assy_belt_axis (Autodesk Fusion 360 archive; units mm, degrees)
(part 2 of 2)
joint "Assemble7" alignAngle 0 alignOffsetX 0 alignOffsetY 0 alignOffsetZ 0
joint "Assemble8" alignAngle 0 alignOffsetX 0 alignOffsetY 0 alignOffsetZ 0
fillet "Fillet6" ChordLen 8
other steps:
joint_origin "JointOrigin1"
joint_origin "JointOrigin2"
joint_origin "JointOrigin3"
joint_origin "JointOrigin4"
joint_origin "JointOrigin5"
joint_origin "JointOrigin6"
joint_origin "JointOrigin7"
named bodies: "belt_motor_mount"

design "PP_SWTC_Omron-V154"
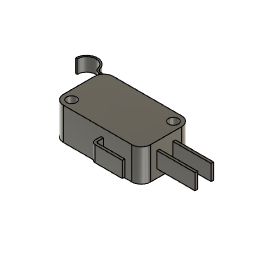
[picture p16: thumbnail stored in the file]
sketch "Sketch1" plane through (0, 0, 0) normal (0, 0, 1) x axis (1, 0, 0)
  line L1 (22.2, 0) -> (0, 0)
  line L2 (22.2, 10.3) -> (22.2, 0)
  line L3 (0, 10.3) -> (22.2, 10.3)
  line L4 (0, 0) -> (0, 10.3)
  line L5 (25, -2.8) -> (-2.8, -2.8)
  line L6 (25, 13.1) -> (25, -2.8)
  line L7 (-2.8, 13.1) -> (25, 13.1)
  line L8 (-2.8, -2.8) -> (-2.8, 13.1)
  line L9 (14.1, 15.2) -> (14.1, 13.1)
  line L10 (-6.9, 15.2) -> (14.1, 15.2)
  line L11 (13.6, 14.7) -> (-7.442, 14.7)
  line L12 (13.6, 13.1) -> (13.6, 14.7)
  line L13 (-13.9, 15.2) -> (-13.4, 15.2)
  line L14 (-10.4, 18.7) -> (-10.4, 15.2)
  line L15 (37.2, 8.1) -> (25, 8.1)
  line L16 (37.2, 7.3) -> (37.2, 8.1)
  line L17 (25, 7.3) -> (37.2, 7.3)
  line L18 (25, 8.1) -> (25, 7.3)
  line L19 (37.2, 3) -> (25, 3)
  line L20 (37.2, 2.2) -> (37.2, 3)
  line L21 (25, 2.2) -> (37.2, 2.2)
  line L22 (25, 3) -> (25, 2.2)
  line L23 (13, -5.2) -> (13, -2.8)
  line L24 (22.2, -5.2) -> (13, -5.2)
  line L25 (22.2, -6) -> (22.2, -5.2)
  line L26 (12.2, -6) -> (22.2, -6)
  line L27 (12.2, -2.8) -> (12.2, -6)
  circle C1 centre (0, 0) radius 2.8
  circle C2 centre (22.2, 10.3) radius 2.8
  circle C3 centre (22.2, 10.3) radius 1.55
  circle C4 centre (0, 0) radius 1.55
  arc A1 centre (-10.4, 15.2) radius 3.5 clockwise from (-13.9, 15.2) to (-6.9, 15.2)
  arc A2 centre (-10.4, 15.2) radius 3 clockwise from (-13.4, 15.2) to (-7.442, 14.7)
  point P1 (0, 0)
  point P2 (0, 0)
  point P10 (0, 0)
  point P4 (22.2, 10.3)
  point P11 (22.2, 10.3)
  point P13 (0, 0)
  point P14 (14.1, 13.1)
  point P18 (-13.9, 15.2)
  point P17 (-10.4, 15.2)
  point P19 (-10.4, 15.2)
  point P23 (13.6, 13.1)
  point P24 (-10.4, 15.2)
  point P25 (-10.4, 18.7)
  point P26 (25, 8.1)
  point P30 (25, 3)
  point P34 (13, -2.8)
  point P39 (12.2, -2.8)
  point P31 (37.2, 3)
  point P3 (22.2, 0)
  point P6 (-2.8, -2.8)
  point P7 (25, -2.8)
  point P9 (-2.8, 13.1)
  point P8 (25, 13.1)
  point P12 (22.2, 10.3)
  point P22 (13.6, 14.7)
  point P15 (14.1, 15.2)
  point P35 (13, -5.2)
  point P32 (37.2, 2.2)
  point P27 (37.2, 8.1)
  point P28 (37.2, 7.3)
  point P37 (22.2, -6)
  horizontal L1
  vertical L2
  horizontal L3
  vertical L4
  coincident P1 P2
  horizontal L5
  vertical L6
  horizontal L7
  vertical L8
  coincident P1 P10
  coincident P4 P11
  concentric C2 C3
  coincident P1 P13
  equal C3 C4
  tangent L7 C2
  tangent L6 C2
  tangent L5 C1
  coincident L7 P14
  perpendicular L7 L9
  perpendicular L9 L10
  coincident L10 P18
  coincident P17 P19
  horizontal L11
  coincident L7 P23
  perpendicular L7 L12
  coincident P19 L13
  horizontal L13
  coincident P19 P24
  midpoint A1 P25
  horizontal L15
  vertical L16
  horizontal L17
  vertical L18
  coincident L6 P26
  horizontal L19
  vertical L20
  horizontal L21
  vertical L22
  coincident L6 P30
  coincident L5 P34
  perpendicular L5 L23
  perpendicular L6 L24
  perpendicular L24 L25
  perpendicular L25 L26
  coincident L5 P39
  perpendicular L5 L27
  coincident L16 P31
  dimension "d2" distance P2 P3 = 22.2
  dimension "d3" distance P3 P4 = 10.3
  dimension "d4" distance P6 P7 = 27.8
  dimension "d5" distance P6 P9 = 15.9
  dimension "d6" diameter C3 = 3.1
  dimension "d7" distance P8 P12 = 2.8
  dimension "d8" distance L9 L12 = 0.5
  dimension "d9" distance L10 P22 = 0.5 (= "d8")
  dimension "d10" distance A1 A2 = 0.5 (= "d8")
  dimension "d11" radius A1 = 3.5
  dimension "d12" distance P10 P25 = 18.7
  dimension "d13" distance P12 P25 = 32.6
  dimension "d14" distance P12 P15 = 8.1
  dimension "d25" distance P35 L27 = 0.8
  dimension "d26" distance P35 L26 = 0.8 (= "d25")
  dimension "d27" distance P31 P32 = 0.8 (= "d25")
  dimension "d28" distance P27 P28 = 0.8 (= "d25")
  dimension "d29" distance P8 P37 = 19.1
  dimension "d30" distance P7 P37 = 2.8
  dimension "d31" distance P7 L23 = 12
  dimension "d33" distance P8 P27 = 5
  dimension "d34" distance P6 P28 = 40
  dimension "d35" distance P7 P32 = 5 (= "d33")
extrude "Extrude1" new body sketch "Sketch1" profile of L5 L6 L7 L8 C3 C4 distance 10.3
extrude "Extrude2" add sketch "Sketch1" profile of L7 L9 L10 A1 A2 L11 L12 L13 distance 4.3
fillet "Fillet1" radius 3
fillet "Fillet2" radius 1
fillet "Fillet3" radius 1.5
extrude "Extrude3" add sketch "Sketch1" profile of L5 L6 L15 L16 L17 L18 L19 L20 L21 L22 L23 L24 L25 L26 L27 distance 5
fillet "Fillet4" radius 0.5
fillet "Fillet5" radius 1.3 (= "0.5 mm + 0.8 mm")

design "carriage_front_generic" references "PP_TRNS_V-Wheel", "HW_M5x20-SHCS"
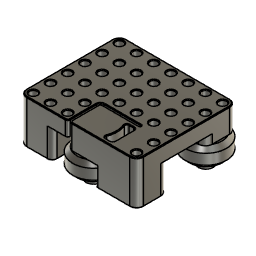
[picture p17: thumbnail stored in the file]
parameter "d19" = 10.75
sketch "Sketch1" plane through (0, 0, 0) normal (0, 0, 1) x axis (1, 0, 0)
  line L1 (0, -29) -> (0, 29)
  line L2 (-34, 29) -> (0, 29)
  line L3 (-34, -29) -> (-34, 29)
  line L4 (0, 10) -> (-34, 10)
  line L5 (0, -10) -> (-34, -10)
  line L6 (-16.2, 11) -> (-34, 11)
  line L7 (-16.2, 29) -> (-16.2, 11)
  line L8 (-34, -29) -> (0, -29)
  line L9 (34, -29) -> (0, -29)
  line L10 (34, -29) -> (34, 29)
  line L11 (16.2, 11) -> (34, 11)
  line L12 (16.2, 29) -> (16.2, 11)
  line L13 (34, 29) -> (0, 29)
  line L14 (17.9222, -13.2) -> (11.9222, -13.2)
  line L15 (17.9222, -26.8) -> (17.9222, -13.2)
  line L16 (11.9791, -26.8) -> (17.9222, -26.8)
  line L17 (-5, -11) -> (17.9222, -11)
  line L18 (17.9222, -10) -> (17.9222, -11)
  line L19 (-6, -10) -> (17.9222, -10)
  line L20 (-6, -29) -> (-6, -10)
  line L21 (34, -11) -> (17.9222, -11)
  line L22 (-5, -29) -> (-5, -11)
  line L23 (12.75, -20.05) -> (0, -20.05)
  line L24 (13.75, -20.05) -> (12.75, -20.05)
  line L25 (30, -25) -> (30, -15)
  line L26 (-30, -25) -> (30, -25)
  line L27 (-15, -11) -> (-34, -11)
  line L28 (-15, -29) -> (-15, -11)
  circle C1 centre (-25.1, 20.1) radius 2.2
  circle C2 centre (0, -20.05) radius 2.2
  circle C3 centre (0, -20.05) radius 12
  circle C4 centre (-25.1, 20.1) radius 12
  circle C5 centre (-25.1, 20.1) radius 4.2
  circle C6 centre (0, -20.05) radius 4.2
  circle C7 centre (0, 25) radius 2.2
  circle C8 centre (25.1, 20.1) radius 4.2
  circle C9 centre (25.1, 20.1) radius 2.2
  arc A1 centre (0, -20.05) radius 12.75 clockwise from (8.9811, -11) to (9.0807, -29)
  arc A2 centre (0, -20.05) radius 13.75 clockwise from (11.9222, -13.2) to (11.9791, -26.8)
  circle C10 centre (-30, -25) radius 2.2
  circle C11 centre (30, -25) radius 2.2
  circle C12 centre (30, -15) radius 2.2
  point P1 (0, 0)
  point P10 (-34, 10)
  point P11 (0, 10)
  point P13 (0, -10)
  point P14 (-34, 11)
  point P16 (-16.2, 29)
  point P19 (0, 25)
  point P9 (-34, -29)
  point P20 (-34, -29)
  point P12 (-34, -10)
  point P18 (0, -20.05)
  point P2 (0, 29)
  point P30 (0, 29)
  point P3 (0, -29)
  point P21 (0, -29)
  point P8 (-34, 29)
  point P23 (34, 29)
  point P24 (34, -29)
  point P27 (34, 11)
  point P15 (-16.2, 11)
  point P28 (16.2, 11)
  point P29 (16.2, 29)
  point P22 (34, -29)
  point P39 (-6, -29)
  point P32 (17.9222, -13.2)
  point P40 (34, -11)
  point P41 (-5, -29)
  point P43 (9.0807, -29)
  point P44 (8.9811, -11)
  point P42 (0, -20.05)
  point P5 (0, -20.05)
  point P45 (0, -20.05)
  point P46 (12.75, -20.05)
  point P47 (0, -20.05)
  point P31 (11.9222, -13.2)
  point P48 (11.9222, -13.2)
  point P49 (13.75, -20.05)
  point P52 (30, -15)
  point P53 (30, -15)
  point P51 (30, -25)
  point P54 (30, -25)
  point P55 (30, -25)
  point P50 (-30, -25)
  point P56 (-30, -25)
  point P57 (-34, -11)
  point P36 (-5, -11)
  point P59 (-15, -29)
  point P4 (-25.1, 20.1)
  point P17 (-25.1, 20.1)
  point P35 (17.9222, -11)
  point P37 (17.9222, -10)
  point P6 (0, -20.05)
  vertical L1
  coincident P1 L1
  equal C1 C2
  concentric C2 C3
  concentric C1 C4
  equal C3 C4
  perpendicular L1 L2
  perpendicular L2 L3
  midpoint P1 L1
  coincident L3 P10
  coincident L1 P11
  perpendicular L1 L4
  coincident L1 P13
  perpendicular L1 L5
  coincident L3 P14
  coincident L2 P16
  perpendicular L2 L7
  concentric C1 C5
  concentric C3 C6
  equal C5 C6
  coincident L1 P19
  perpendicular L1 L8
  coincident P9 P20
  coincident L3 P12
  horizontal L6
  coincident L1 P18
  symmetric P2 L1 P30
  symmetric P3 L1 P21
  symmetric L1 C1 C9
  symmetric L1 P8 P23
  symmetric L1 P9 P24
  symmetric L1 P14 P27
  symmetric L1 P15 P28
  symmetric L1 P16 P29
  symmetric L1 C5 C8
  symmetric L1 P20 P22
  horizontal L14
  vertical L15
  horizontal L16
  horizontal L17
  perpendicular L17 L18
  perpendicular L18 L19
  coincident L8 P39
  perpendicular L8 L20
  coincident P32 L18
  coincident L10 P40
  perpendicular L10 L21
  coincident L8 P41
  perpendicular L8 L22
  coincident L9 P43
  coincident L17 P44
  coincident P18 P42
  coincident P5 P45
  coincident A1 P46
  coincident P42 P47
  coincident P31 P48
  coincident A2 P49
  parallel L23 L24
  horizontal L23
  equal C10 C11
  coincident P52 P53
  coincident P51 P54
  vertical L25
  coincident P51 P55
  coincident P50 P56
  horizontal L26
  equal C11 C12
  coincident L3 P57
  perpendicular L3 L27
  coincident P36 L27
  coincident L8 P59
  perpendicular L8 L28
  dimension "d1" distance P1 P4 = 20.1
  dimension "d2" distance P1 P5 = 20.05 (= "d1 - 0.05 mm")
  dimension "d3" diameter C1 = 4.4
  dimension "d4" diameter C4 = 24
  dimension "d11" distance P2 P8 = 34
  dimension "d17" distance P1 L4 = 10
  dimension "d18" distance P1 P13 = 10
  dimension "d28" distance C1 C5 = 2
  dimension "d73" diameter C7 = 4.4
  dimension "d76" distance P1 P19 = 25
  dimension "d133" distance P2 P19 = 4
  dimension "d134" distance P2 P4 = 25.1
  dimension "d135" distance P1 P2 = 29
  dimension "d136" distance P4 L2 = 8.9
  dimension "d137" distance P8 P17 = 8.9 (= "d136")
  dimension "d138" distance L7 P17 = 8.9 (= "d137")
  dimension "d139" distance P10 L6 = 1
  dimension "d140" distance L9 L16 = 2.2
  dimension "d141" distance L14 L17 = 2.2 (= "d140")
  dimension "d142" distance P31 P32 = 6
  dimension "d143" distance L5 L17 = 1
  dimension "d146" distance C3 A1 = 0.75
  dimension "d147" distance P46 P49 = 1
  dimension "d148" distance P35 P37 = 1
  dimension "d154" distance P6 L8 = 8.95
  dimension "d155" distance P6 L22 = 5
  dimension "d156" distance L20 P41 = 1 (= "d148")
  dimension "d167" distance P1 P50 = 25
  dimension "d168" distance L1 P50 = 30
  dimension "d169" diameter C10 = 4.4
  dimension "d192" distance P21 P51 = 30
  dimension "d193" distance P53 P54 = 10
  dimension "d202" distance P50 L28 = 15
extrude "Extrude1" new body sketch "Sketch1" profile of C1 C2 L2 L3 L6 L7 C5 C6 C7 L8 L9 L10 C8 C9 L11 L12 L13 L14 L15 L16 L17 L18 L19 L20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 blind 9 from offset 11
extrude "Extrude2" add sketch "Sketch1" profile of C1 C2 L2 L3 L6 L7 C5 C6 L8 L9 L10 C8 C9 L11 L12 L13 L14 L15 L16 L17 L21 L22 to an object from offset 5.5 (= "( 11 / 2 ) * 1 mm")
extrude "Extrude3" sketch "Sketch1" profile of L2 L3 L6 L7 C5 C6 L8 L9 L10 C8 L11 L12 L13 L14 L15 L16 L17 L21 L22 blind 0.6
extrude "Extrude5" sketch "Sketch1" profile of L9 L10 L14 L15 L16 L17 L21 A1 A2 to an object offset 11
fillet "Fillet4" ChordLen 2
fillet "Fillet2" radius 4
fillet "Fillet3" radius 4
chamfer "Chamfer3" distance 0.5
fillet "Fillet5" ChordLen 2
fillet "Fillet6" ChordLen 3
fillet "Fillet7" ChordLen 0.5
extrude "Extrude6" sketch "Sketch1" profile of C10 to an object
rectangular_pattern "R-Pattern3" uSpaceDistance 10 vSpaceDistance 10
extrude "Extrude7" sketch "Sketch1" profile of C1 C2 C9 blind -1
extrude "Extrude8" sketch "Sketch1" profile of L3 L8 C10 L27 to an object
fillet "Fillet8" ChordLen 6
extrude "Extrude9" cut of existing geometry to an object
extrude "Extrude10" cut of existing geometry to an object
chamfer "Chamfer4" distance 2.2
fillet "Fillet9" ChordLen 4
chamfer "Chamfer5" distance 0.4
chamfer "Chamfer6" distance 0.4
chamfer "Chamfer7" distance 0.5
component_insert "Component Insert3"
component_insert "Component Insert4"
component_insert "Component Insert5"
component_insert "Component Insert11"
component_insert "Component Insert12"
component_insert "Component Insert14"
joint "Assemble14" alignAngle 0 alignOffsetX 0 alignOffsetY 0 alignOffsetZ 0
joint "Assemble17" alignAngle 180 alignOffsetX 0 alignOffsetY 0 alignOffsetZ 0
joint "Assemble18" alignAngle 0 alignOffsetX 0 alignOffsetY 0 alignOffsetZ 0
joint "Assemble19" alignAngle 0 alignOffsetX 0 alignOffsetY 0 alignOffsetZ 0
joint "Assemble21" alignAngle 0 alignOffsetX 0 alignOffsetY 0 alignOffsetZ 0
joint "Assemble22" alignAngle 0 alignOffsetX 0 alignOffsetY 0 alignOffsetZ 0
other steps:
joint_origin "JointOrigin12"
joint_origin "JointOrigin15"
joint_origin "JointOrigin16"
named bodies: "carriage_front_generic"

design "HW_M5-Washer"
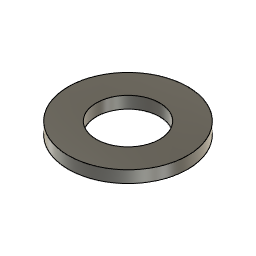
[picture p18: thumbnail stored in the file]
sketch "Sketch1" plane through (0, 0, 0) normal (0, 1, 0) x axis (1, 0, 0)
  line L1 (5, 0) -> (2.65, 0)
  line L2 (5, -1) -> (5, 0)
  line L3 (2.65, -1) -> (5, -1)
  line L4 (2.65, 0) -> (2.65, -1)
  point P1 (0, 0)
  point P2 (2.65, 0)
  point P5 (2.65, -1)
  horizontal L1
  vertical L2
  horizontal L3
  vertical L4
  coincident P1 L1
  dimension "d1" distance P2 P5 = 1
  dimension "d2" distance P1 L4 = 2.65 (= "( 5.3 / 2 ) * 1 mm")
  dimension "d3" distance P1 L2 = 5 (= "( 10 / 2 ) * 1 mm")
revolve "Revolve1" sketch "Sketch1" AlongAngle 360

design "PP_TRNS_GT2-Pulley-20T-6mm"
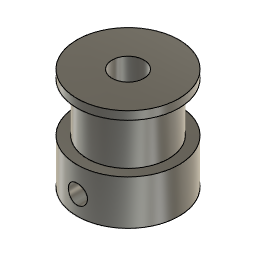
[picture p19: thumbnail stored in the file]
sketch "Sketch1" plane through (0, 0, 0) normal (0, 1, 0) x axis (1, 0, 0)
  line L1 (8, 0) -> (0, 0)
  line L2 (8, -7) -> (8, 0)
  line L3 (6.3662, -7) -> (8, -7)
  line L4 (6.3662, -14.7) -> (6.3662, -7)
  line L5 (8, -14.7) -> (6.3662, -14.7)
  line L6 (8, -16) -> (8, -14.7)
  line L7 (2.5, -16) -> (8, -16)
  line L8 (2.5, 0) -> (2.5, -16)
  line L9 (0, -3) -> (0, 0)
  circle C1 centre (0, -3) radius 1.5
  point P1 (0, 0)
  point P2 (0, 0)
  point P10 (2.5, 0)
  point P4 (8, -7)
  point P12 (0, 0)
  point P11 (0, -3)
  point P13 (0, -3)
  point P3 (8, 0)
  point P7 (8, -14.7)
  point P8 (8, -16)
  coincident P1 P2
  horizontal L1
  perpendicular L1 L2
  perpendicular L2 L3
  perpendicular L3 L4
  perpendicular L4 L5
  perpendicular L5 L6
  perpendicular L4 L7
  coincident L1 P10
  perpendicular L1 L8
  coincident P4 L6
  coincident P1 P12
  coincident P11 P13
  vertical L9
  dimension "d1" distance P1 L8 = 2.5 (= "( 5 / 2 ) * 1 mm")
  dimension "d2" distance P1 L2 = 8 (= "( 16 / 2 ) * 1 mm")
  dimension "d3" distance P3 P4 = 7
  dimension "d4" distance P1 L4 = 6.3662 (= "( 20 * 2 / PI ) * 1 mm / 2")
  dimension "d5" distance P7 P8 = 1.3
  dimension "d6" distance P3 L7 = 16
  dimension "d8" diameter C1 = 3
  dimension "d9" distance P12 P13 = 3
revolve "Revolve1" sketch "Sketch1" AlongAngle 360
extrude "Extrude1" cut sketch "Sketch1" profile of C1 against normal blind 17

design "belt_idler" references "HW_M5-Washer", "PP_BRNG_625F-5x16x5", "HW_M5x10-SHCS", "HW_M5x20-SHCS"
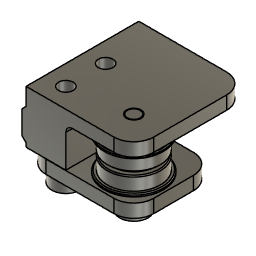
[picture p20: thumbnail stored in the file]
sketch "Sketch1" plane through (0, 0, 0) normal (0, 0, 1) x axis (1, 0, 0)
  line L1 (0, 0) -> (23.5, 0)
  line L2 (0, 25) -> (0, -9)
  line L3 (32.5, 25) -> (0, 25)
  line L4 (32.5, -9) -> (32.5, 25)
  line L5 (0, -9) -> (32.5, -9)
  line L6 (5, 25) -> (5, -9)
  line L7 (12, 25) -> (12, -9)
  line L8 (6, 9) -> (6, -3)
  line L9 (0, 15) -> (12, 15)
  line L10 (32.5, 15) -> (12, 15)
  circle C1 centre (23.5, 0) radius 8.5
  circle C2 centre (23.5, 0) radius 7.5
  circle C3 centre (23.5, 0) radius 2.55
  circle C4 centre (23.5, 0) radius 3.55
  circle C5 centre (23.5, 0) radius 2.2
  circle C6 centre (6, -3) radius 2.2
  circle C7 centre (6, -3) radius 5
  circle C8 centre (6, -3) radius 2.75
  circle C9 centre (6, 9) radius 2.75
  circle C10 centre (6, 9) radius 2.2
  circle C11 centre (6, 9) radius 5
  point P2 (23.5, 0)
  point P3 (23.5, 0)
  point P4 (23.5, 0)
  point P1 (0, 0)
  point P5 (0, 0)
  point P6 (15, 0)
  point P7 (0, -9)
  point P11 (0, -9)
  point P12 (23.5, 0)
  point P15 (5, -9)
  point P16 (5, 25)
  point P18 (12, -9)
  point P19 (12, 25)
  point P22 (6, -3)
  point P26 (6, -3)
  point P24 (6, 9)
  point P27 (6, 9)
  point P28 (12, 15)
  point P29 (0, 15)
  point P30 (6, 3)
  point P31 (32.5, 15)
  point P13 (23.5, 0)
  point P9 (32.5, 25)
  point P10 (32.5, -9)
  point P21 (6, -3)
  point P23 (6, 9)
  coincident P2 P3
  coincident P2 P4
  coincident P1 P5
  horizontal L1
  coincident C1 P6
  coincident L1 P6
  perpendicular L2 L3
  perpendicular L3 L4
  perpendicular L4 L5
  coincident P7 P11
  coincident P2 P12
  concentric C2 C3
  coincident P1 L2
  vertical L2
  concentric C1 C4
  coincident L5 P15
  coincident L3 P16
  perpendicular L3 L6
  concentric C1 C5
  coincident L5 P18
  coincident L3 P19
  perpendicular L3 L7
  concentric C6 C7
  concentric C6 C8
  concentric C9 C10
  concentric C9 C11
  equal C7 C11
  coincident P22 P26
  coincident P24 P27
  vertical L8
  equal C6 C10
  equal C8 C9
  coincident L7 P28
  coincident L2 P29
  perpendicular L2 L9
  midpoint L8 P30
  coincident L4 P31
  perpendicular L4 L10
  dimension "d2" distance P1 P6 = 15
  dimension "d38" distance C1 C2 = 1
  dimension "d39" diameter C2 = 15
  dimension "d40" diameter C3 = 5.1
  dimension "d41" distance L4 P13 = 9
  dimension "d42" distance L5 P13 = 9
  dimension "d43" distance C3 C4 = 1
  dimension "d44" distance P7 P15 = 5
  dimension "d46" distance P9 P10 = 34
  dimension "d48" diameter C5 = 4.4
  dimension "d63" distance P6 L7 = 3
  dimension "d64" diameter C7 = 10
  dimension "d65" diameter C6 = 4.4
  dimension "d66" diameter C8 = 5.5
  dimension "d67" distance P7 P22 = 6
  dimension "d68" distance P7 P21 = 6
  dimension "d69" distance P26 P27 = 12
  dimension "d78" distance P23 L9 = 6
extrude "Extrude1" new body sketch "Sketch1" profile of L2 L3 L4 L5 C3 C4 L6 C5 L7 C6 C8 C9 C10 L9 L10 along normal blind 4 bodies "belt_idler_body"
extrude "Extrude2" sketch "Sketch1" profile of L2 L3 L5 L6 blind -20
extrude "Extrude4" add sketch "Sketch1" profile of C3 C4 C5 against normal blind 0.5
chamfer "Chamfer5" distance 0.4 distance 1
component_insert "Component Insert3"
joint "Assemble3" alignAngle 0 alignOffsetX 0 alignOffsetY 0 alignOffsetZ 0
component_insert "Component Insert4"
joint "Assemble4" alignAngle 0 alignOffsetX 0 alignOffsetY 0 alignOffsetZ 0
component_insert "Component Insert5"
joint "Assemble5" alignAngle 0 alignOffsetX 0 alignOffsetY 0 alignOffsetZ 0
extrude "Extrude5" add sketch "Sketch1" profile of L3 L5 L6 L7 C6 C8 C9 C10 to an object
sketch "Sketch2" plane through (0, 0, 0) normal (-1, 0, 0) x axis (0, -1, 0)
  line L1 (9, 4) -> (9, -16)
  line L2 (-25, 4) -> (9, 4)
  line L3 (-25, -16) -> (-25, 4)
  line L4 (9, -16) -> (-25, -16)
  line L5 (-25, -6) -> (9, -6)
  line L6 (-3, -6) -> (-3, 0)
  line L7 (-19, -12.7175) -> (-22.3588, -9.3588)
  line L8 (-15.6412, -9.3588) -> (-19, -12.7175)
  line L9 (-19, -6) -> (-19, -12.7175)
  line L10 (-19, -9.8891) -> (-20.9445, -7.9445)
  line L11 (-19, -9.8891) -> (-17.0555, -7.9445)
  circle C1 centre (-19, -6) radius 2.75
  circle C2 centre (-19, -6) radius 4.75
  circle C3 centre (-3, -6) radius 2.75
  circle C4 centre (-3, -6) radius 4.75
  point P6 (9, -6)
  point P7 (-25, -6)
  point P8 (-19, -6)
  point P10 (-3, -6)
  point P12 (-3, 0)
  point P13 (-3, 0)
  point P11 (-3, -6)
  point P14 (-3, -6)
  point P15 (-22.3588, -9.3588)
  point P17 (-15.6412, -9.3588)
  point P18 (-19, -6)
  point P19 (-20.9445, -7.9445)
  point P20 (-19, -9.8891)
  point P21 (-17.0555, -7.9445)
  point P4 (-25, 4)
  point P9 (-19, -6)
  midpoint L1 P6
  midpoint L3 P7
  coincident L5 P8
  concentric C1 C2
  coincident L5 P10
  concentric C3 C4
  equal C2 C4
  equal C1 C3
  coincident P12 P13
  coincident P11 P14
  vertical L6
  coincident C2 P15
  tangent C2 L7
  coincident C2 P17
  tangent C2 L8
  perpendicular L7 L8
  coincident P8 P18
  vertical L9
  coincident C1 P19
  coincident L9 P20
  tangent C1 L10
  coincident C1 P21
  perpendicular L10 L11
  tangent C1 L11
  dimension "d17" distance P4 P9 = 6
  dimension "d19" diameter C1 = 5.5
  dimension "d20" diameter C2 = 9.5
extrude "Extrude3" cut sketch "Sketch2" profile of C1 L10 L11 no distance stored
extrude "Extrude6" cut sketch "Sketch2" profile of C1 C2 L7 L8 L10 L11 no distance stored from offset -5
extrude "Extrude7" sketch "Sketch1" profile of L6 C6 C10 to an object
extrude "Extrude8" sketch "Sketch1" profile of L2 L5 L6 L7 C6 C8 C9 C10 L9 blind 4.1
offset_faces "OffsetFaces1" distance -0.1
extrude "Extrude9" sketch "Sketch1" profile of L2 L4 L5 C3 C4 L6 L7 C8 C9 L9 L10 blind 4 bodies "belt_idler_cap"
extrude "Extrude10" sketch "Sketch1" profile of C3 C4 blind 0.5
fillet "Fillet4" radius 1
fillet "Fillet5" radius 6
fillet "Fillet6" radius 6
fillet "Fillet7" radius 2
sketch "Sketch4" plane through (0, 25, 0) normal (0, 1, 0) x axis (-1, 0, 0)
  line L1 (-26.5, 0) -> (-26.5, 4)
  line L2 (-14, 0) -> (-26.5, 0)
  line L3 (-12, -16) -> (-12, -2)
  line L4 (0, -16) -> (-12, -16)
  line L5 (0, 4) -> (0, -16)
  line L6 (-26.5, 4) -> (0, 4)
  line L7 (2, -6) -> (0, -6)
  line L8 (2, -8.75) -> (0, -10.75)
  line L9 (2, -3.25) -> (2, -8.75)
  line L10 (0, -1.25) -> (2, -3.25)
  line L11 (1.25, -2.5) -> (1.25, -9.5)
  arc A1 centre (-14, -2) radius 2 clockwise from (-14, 0) to (-12, -2)
  point P10 (0, -6)
  point P12 (0, -10.75)
  point P15 (0, -1.25)
  point P11 (2, -6)
  point P16 (1.25, -9.5)
  point P17 (1.25, -2.5)
  point P13 (2, -8.75)
  point P14 (2, -3.25)
  midpoint L5 P10
  perpendicular L5 L7
  coincident L5 P12
  parallel L5 L9
  coincident L5 P15
  perpendicular L8 L10
  midpoint P11 L9
  coincident L8 P16
  vertical L11
  coincident L10 P17
  dimension "d112" distance P10 P11 = 2
  dimension "d113" angle L8 L9 = 45
  dimension "d114" distance P10 L11 = 1.25
  dimension "d115" distance P13 P14 = 5.5
extrude "Extrude11" add sketch "Sketch4" profile of L5 L8 L10 L11 to an object
extrude "Extrude12" cut of existing geometry blind -10
fillet "Fillet8" ChordLen 0.5
component_insert "Component Insert9"
joint "Assemble9" alignAngle 0 alignOffsetX 0 alignOffsetY 0 alignOffsetZ 0
component_insert "Component Insert10"
component_insert "Component Insert11"
joint "Assemble10" alignAngle 0 alignOffsetX 0 alignOffsetY 0 alignOffsetZ 0
joint "Assemble11" alignAngle 0 alignOffsetX 0 alignOffsetY 0 alignOffsetZ 0
component_insert "Component Insert12"
joint "Assemble12" alignAngle 0 alignOffsetX 0 alignOffsetY 0 alignOffsetZ 0
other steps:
joint_origin "JointOrigin2"
joint_origin "JointOrigin6"
joint_origin "JointOrigin7"
joint_origin "JointOrigin8"
joint_origin "JointOrigin9"
named bodies: "belt_idler_body", "belt_idler_cap"

design "HW_M3x16-SHCS"
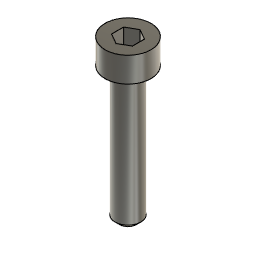
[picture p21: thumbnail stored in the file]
sketch "Sketch1" plane through (0, 0, 0) normal (0, 1, 0) x axis (1, 0, 0)
  line L1 (0, 16) -> (0, -3)
  line L2 (1.05, 16) -> (0, 16)
  line L3 (1.55, 15.5) -> (1.05, 16)
  line L4 (1.55, 0) -> (1.55, 15.5)
  line L5 (2.75, 0) -> (1.55, 0)
  line L6 (2.75, -3) -> (2.75, 0)
  line L7 (0, -3) -> (2.75, -3)
  point P1 (0, 0)
  point P4 (1.05, 16)
  point P5 (1.55, 15.5)
  point P3 (0, 16)
  point P7 (2.75, 0)
  point P8 (2.75, -3)
  point P2 (0, -3)
  vertical L1
  perpendicular L1 L2
  perpendicular L2 L4
  perpendicular L4 L5
  perpendicular L5 L6
  horizontal L7
  coincident P1 L1
  coincident P1 L5
  dimension "d1" distance P1 L2 = 16
  dimension "d2" angle L2 L3 = 45
  dimension "d3" distance P4 P5 = 0.5
  dimension "d4" distance P3 L4 = 1.55 (= "( 3.1 / 2 ) * 1 mm")
  dimension "d5" distance P7 P8 = 3
  dimension "d6" distance P2 P8 = 2.75 (= "( 5.5 / 2 ) * 1 mm")
revolve "Revolve1" sketch "Sketch1" AlongAngle 360
sketch "Sketch2" plane through (0, 0, 3) normal (0, 0, 1) x axis (-1, 0, 0)
  line L1 (0, -1.4434) -> (-1.25, -0.7217)
  line L2 (1.25, -0.7217) -> (0, -1.4434)
  line L3 (1.25, 0.7217) -> (1.25, -0.7217)
  line L4 (0, 1.4434) -> (1.25, 0.7217)
  line L5 (-1.25, 0.7217) -> (0, 1.4434)
  line L6 (-1.25, -0.7217) -> (-1.25, 0.7217)
  circle C1 centre (0, 0) radius 2.75
  point P1 (0, 0)
  point P9 (0, 0)
  point P5 (1.25, -0.7217)
  coincident P1 P9
  vertical L6
  dimension "d8" distance P5 L6 = 2.5
extrude "Extrude1" cut sketch "Sketch2" profile of L1 L2 L3 L4 L5 L6 against normal blind 2

design "belt_clip_update" references "HW_M5x25-SHCS", "HW_M5x10-SHCS"
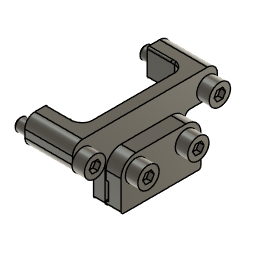
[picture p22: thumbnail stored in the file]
sketch "Sketch1" plane through (0, 0, 0) normal (0, 0, 1) x axis (1, 0, 0)
  line L1 (0, 29) -> (0, 0)
  line L2 (25.5, 29) -> (0, 29)
  line L3 (25.5, 0) -> (25.5, 29)
  line L4 (0, 0) -> (25.5, 0)
  line L5 (20.5, 29) -> (20.5, 0)
  line L6 (19.1, 0) -> (19.1, 29)
  line L7 (19.5, 29) -> (19.5, 0)
  line L8 (1, 29) -> (1, 0)
  line L9 (4.5, 29) -> (4.5, 0)
  line L10 (20.5, 1) -> (19.1, 1)
  line L11 (19.75, 0.7402) -> (19.75, 1)
  line L12 (21.5, 1) -> (20.5, 1)
  line L13 (21.5, 0) -> (21.5, 1)
  line L14 (21.5, 29) -> (21.5, 1)
  line L15 (9.5, 0) -> (9.5, 29)
  line L16 (25.5, 25) -> (0, 25)
  arc A1 centre (19.945, 0) radius 0.555 clockwise from (20.1882, 0.4989) to (20.5, 0)
  arc A2 centre (19.75, -0.4) radius 1 clockwise from (19.8804, 0.5915) to (20.1882, 0.4989)
  arc A3 centre (19.9, 0.7402) radius 0.15 clockwise from (19.8804, 0.5915) to (19.75, 0.7402)
  point P1 (0, 0)
  point P2 (0, 0)
  point P6 (0, 0)
  point P7 (20.5, 0)
  point P8 (20.5, 29)
  point P9 (19.1, 29)
  point P10 (19.1, 0)
  point P11 (19.5, 0)
  point P12 (19.5, 29)
  point P13 (1, 0)
  point P14 (1, 29)
  point P15 (4.5, 0)
  point P16 (4.5, 29)
  point P17 (19.1, 1)
  point P18 (20.5, 1)
  point P19 (19.75, 1)
  point P27 (21.5, 0)
  point P28 (21.5, 29)
  point P29 (9.5, 29)
  point P30 (9.5, 0)
  point P31 (0, 25)
  point P32 (25.5, 25)
  point P4 (25.5, 29)
  point P24 (19.75, -0.4)
  point P26 (21.5, 1)
  coincident P1 P2
  vertical L1
  perpendicular L1 L2
  perpendicular L2 L3
  perpendicular L3 L4
  coincident P1 P6
  coincident L4 P7
  coincident L2 P8
  perpendicular L2 L5
  coincident L2 P9
  coincident L4 P10
  perpendicular L4 L6
  coincident L4 P11
  coincident L2 P12
  perpendicular L2 L7
  coincident L4 P13
  perpendicular L4 L8
  coincident L2 P14
  coincident L4 P15
  coincident L2 P16
  perpendicular L2 L9
  coincident L6 P17
  perpendicular L5 L10
  coincident L5 P18
  coincident L10 P19
  perpendicular L10 L11
  tangent L5 A1
  tangent A1 A2
  tangent L11 A3
  tangent A2 A3
  perpendicular L5 L12
  perpendicular L4 L13
  coincident L4 P27
  coincident L2 P28
  perpendicular L2 L14
  coincident L2 P29
  perpendicular L4 L15
  coincident L4 P30
  coincident L1 P31
  coincident L3 P32
  perpendicular L3 L16
  dimension "d2" distance P4 P8 = 5
  dimension "d3" distance P7 P10 = 1.4
  dimension "d4" distance P1 L8 = 1
  dimension "d5" distance P14 P16 = 3.5 (= "20 mm - 16.5 mm")
  dimension "d6" distance P12 P16 = 15
  dimension "d7" distance P10 P11 = 0.4
  dimension "d8" distance P7 P18 = 1
  dimension "d9" radius A1 = 0.555
  dimension "d10" radius A2 = 1
  dimension "d11" radius A3 = 0.15
  dimension "d12" distance L4 P24 = 0.4
  dimension "d13" distance P11 L11 = 0.25
  dimension "d22" distance P18 P26 = 1
  dimension "d36" distance P16 L15 = 5
  dimension "d75" distance P1 P31 = 25
  dimension "d76" distance L2 P31 = 4
extrude "Extrude1" new body sketch "Sketch1" profile of L1 L2 L4 L6 L15 blind 11 from offset 1 bodies "belt_clip_bod"
extrude "Extrude2" new body sketch "Sketch1" profile of L4 L5 L10 L11 A1 A2 A3 L12 L13 blind -7 from offset -6.5 bodies "belt_clip_cap"
mirror "Mirror1" mirrorStitchTolerance 0.1
rectangular_pattern "R-Pattern1" uSpaceDistance 2 vSpaceDistance 0
combine "Combine1"
extrude "Extrude3" sketch "Sketch1" profile of L2 L3 L4 L5 L7 L10 L11 A1 A2 A3 L12 L13 L14 blind -2
extrude "Extrude4" sketch "Sketch1" profile of L2 L3 L4 L13 L14 to an object
extrude "Extrude5" sketch "Sketch1" profile of L2 L3 L4 L5 L7 L10 L11 A1 A2 A3 L12 L13 L14 to an object
extrude "Extrude12" cut of existing geometry to an object
extrude "Extrude6" sketch "Sketch1" profile of L2 L4 L6 L15 to an object
sketch "Sketch2" plane through (0, 0, 0) normal (-1, 0, 0) x axis (0, -1, 0)
  line L1 (0, 1) -> (-29, 1)
  line L2 (0, 12) -> (0, 1)
  line L3 (-29, 12) -> (0, 12)
  line L4 (-29, 1) -> (-29, 12)
  line L5 (-20, 1) -> (-20, 12)
  line L6 (-20, -15.5) -> (-20, 1)
  line L7 (0, -15.5) -> (-29, -15.5)
  line L8 (0, 1) -> (0, -15.5)
  line L9 (-29, 1) -> (0, 1)
  line L10 (-29, -15.5) -> (-29, 1)
  circle C1 centre (-25, 5) radius 2.75
  circle C2 centre (-25, 5) radius 5
  point P8 (-20, 12)
  point P9 (-20, 1)
  point P10 (-20, -15.5)
  point P1 (0, 0)
  point P6 (-25, 5)
  concentric C1 C2
  coincident L3 P8
  coincident L1 P9
  perpendicular L1 L5
  vertical L6
  coincident P10 L7
  dimension "d40" distance P1 P6 = 25
  dimension "d41" distance P1 P6 = 5
  dimension "d42" diameter C1 = 5.5
  dimension "d61" diameter C2 = 10
  dimension "d81" distance L2 L5 = 20
sketch "Sketch3" plane through (25.5, 0, 0) normal (1, 0, 0) x axis (0, 1, 0)
  line L1 (0, -15.5) -> (0, 12)
  line L2 (16, -15.5) -> (0, -15.5)
  line L3 (16, 12) -> (16, -15.5)
  line L4 (0, 12) -> (16, 12)
  line L5 (0, 3) -> (16, 3)
  circle C1 centre (10, -3) radius 2.2
  circle C2 centre (10, -3) radius 5
  circle C3 centre (10, -3) radius 2.75
  point P9 (16, 3)
  point P10 (0, 3)
  point P1 (0, 0)
  point P8 (10, -3)
  point P4 (16, -15.5)
  point P6 (10, -3)
  concentric C1 C2
  concentric C1 C3
  coincident L3 P9
  coincident L1 P10
  perpendicular L1 L5
  dimension "d49" diameter C2 = 10
  dimension "d50" diameter C3 = 5.5
  dimension "d51" diameter C1 = 4.4
  dimension "d52" distance P1 P8 = 3
  dimension "d54" distance P4 P6 = 6
  dimension "d55" distance P8 P9 = 6
extrude "Extrude8" cut sketch "Sketch3" profile of C1 to an object
extrude "Extrude9" cut sketch "Sketch3" profile of L1 L3 L4 C1 C3 L5 against normal blind 6
extrude "Extrude10" cut sketch "Sketch2" profile of C1 to an object
extrude "Extrude15" cut sketch "Sketch2" profile of L1 L6 L7 L9 L10 to an object
extrude "Extrude14" cut sketch "Sketch2" profile of L1 L2 L3 L5 to an object
extrude "Extrude16" cut of existing geometry to an object
fillet "Fillet1" radius 6
fillet "Fillet2" radius 1
fillet "Fillet3" radius 4
fillet "Fillet4" ChordLen 3
fillet "Fillet5" ChordLen 1
chamfer "Chamfer3" distance 0.5
mirror "Mirror3" mirrorStitchTolerance 0.1
extrude "Extrude11" cut of existing geometry blind -5
fillet "Fillet6" ChordLen 5
component_insert "Component Insert1"
component_insert "Component Insert2"
joint "Assemble1" alignAngle 180 alignOffsetX 0 alignOffsetY 0 alignOffsetZ 0
joint "Assemble2" alignAngle 0 alignOffsetX 0 alignOffsetY 0 alignOffsetZ 0
component_insert "Component Insert3"
joint "Assemble3" alignAngle 0 alignOffsetX 0 alignOffsetY 0 alignOffsetZ 0
component_insert "Component Insert4"
joint "Assemble4" alignAngle 0 alignOffsetX 0 alignOffsetY 0 alignOffsetZ 0
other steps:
joint_origin "JointOrigin1"
joint_origin "JointOrigin2"
joint_origin "JointOrigin3"
joint_origin "JointOrigin4"
named bodies: "belt_clip_bod", "belt_clip_cap"

design "circuit_modular_stepper"
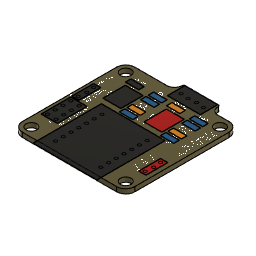
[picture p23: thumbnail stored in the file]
sketch "Outline" plane through (0, 0, 0) normal (0, 0, 1) x axis (1, 0, 0)
  line L1 (35, 1) -> (4, 1)
  line L2 (38, 35) -> (38, 4)
  line L3 (31, 38) -> (35, 38)
  line L4 (17.5, 41) -> (28.5, 41)
  line L5 (4, 38) -> (14.5, 38)
  line L6 (1, 4) -> (1, 35)
  arc A1 centre (4, 4) radius 3 clockwise from (4, 1) to (1, 4)
  arc A2 centre (35, 4) radius 3 clockwise from (38, 4) to (35, 1)
  arc A3 centre (35, 35) radius 3 clockwise from (35, 38) to (38, 35)
  arc A4 centre (31.25, 40.25) radius 2.2638 clockwise from (31, 38) to (29, 40.5)
  arc A5 centre (28.5, 40.5) radius 0.5 clockwise from (28.5, 41) to (29, 40.5)
  arc A6 centre (17.5, 40.5) radius 0.5 clockwise from (17, 40.5) to (17.5, 41)
  arc A7 centre (14.5, 40.5) radius 2.5 clockwise from (17, 40.5) to (14.5, 38)
  arc A8 centre (4, 35) radius 3 clockwise from (1, 35) to (4, 38)
canvas "Canvas1"
canvas "Canvas2"
pcbhole "PCBHole1" HoleDepth 1.606 HoleDiameter 3.5 TipAngle 10313.2
pcbhole "PCBHole2" HoleDepth 1.606 HoleDiameter 3.5 TipAngle 10313.2
pcbhole "PCBHole3" HoleDepth 1.606 HoleDiameter 3.5 TipAngle 10313.2
pcbhole "PCBHole4" HoleDepth 1.606 HoleDiameter 3.5 TipAngle 10313.2
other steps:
pcbextrude "PCBExtrude1"
pcbextrude "PCBExtrude1"
extrude "Extrude1" sketch "Outline" blind 1.5 bodies "Board"
box_primitive "BoxPrimitive1" DistanceX 7.1628 DistanceY 2.3368 DistanceZ 0.1 OffsetDistanceX 0 OffsetDistanceY 0
box_primitive "BoxPrimitive1" DistanceX 10.827 DistanceY 5.727 DistanceZ 0.1 OffsetDistanceX 0 OffsetDistanceY 0
box_primitive "BoxPrimitive1" DistanceX 5.353 DistanceY 9.7028 DistanceZ 0.1 OffsetDistanceX 0 OffsetDistanceY 0
box_primitive "BoxPrimitive1" DistanceX 4.4 DistanceY 1.8 DistanceZ 0.1 OffsetDistanceX 0 OffsetDistanceY 0
box_primitive "BoxPrimitive1" DistanceX 7.35 DistanceY 5.8597 DistanceZ 0.1 OffsetDistanceX 0 OffsetDistanceY 0
box_primitive "BoxPrimitive1" DistanceX 22.4638 DistanceY 20.955 DistanceZ 0.1 OffsetDistanceX 0 OffsetDistanceY 0
pcbextrude "PCBExtrude1"
pcbextrude "PCBExtrude2" bodies "CopperHoles"
create_component "CreateComponent1"
create_component "CreateComponent2"
create_component "CreateComponent3"
create_component "CreateComponent4"
create_component "CreateComponent1"
create_component "CreateComponent2"
create_component "CreateComponent3"
create_component "CreateComponent4"
create_component "CreateComponent5"
create_component "CreateComponent6"
as_built_joint "As-built1"
named bodies: "Board", "CopperHoles"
